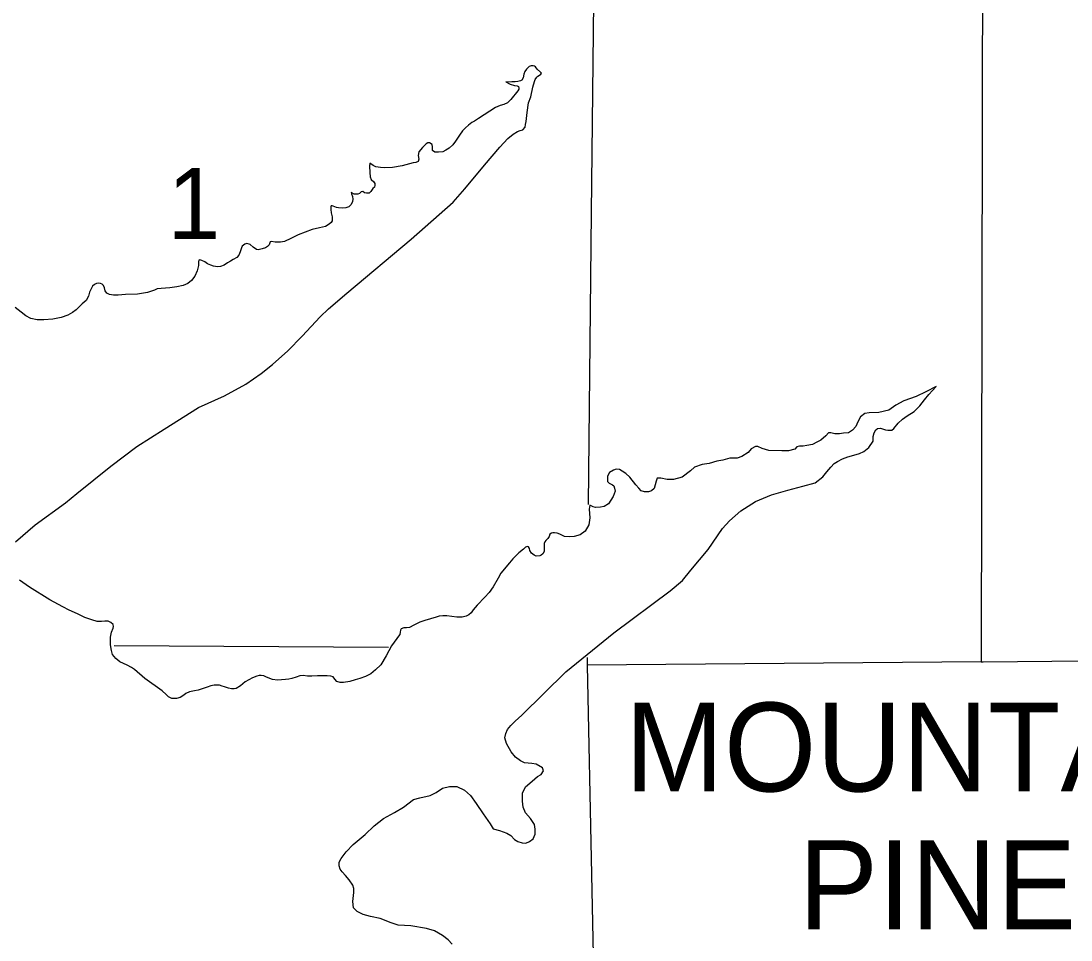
# Model space of a CAD drawing. Extents: x -3711 to 825, y -151 to 1050.
# Drawn here: x -2988.5 to -2918.5, y 182.5 to 243.7 of the extents above; entities that cross this region are included whole.
import ezdxf

# ---------------------------------------------------------------- set-up
doc = ezdxf.new("R2010")
doc.units = 0
for name, color, linetype in [('Level 4', 7, 'Continuous'), ('Level 5', 7, 'Continuous'), ('Level 6', 7, 'Continuous'), ('Level 8', 7, 'Continuous'), ('Level 9', 7, 'Continuous')]:
    doc.layers.add(name, color=color, linetype=linetype)

msp = doc.modelspace()

# ---------------------------------------------------------------- linework, layer by layer
at = {"layer": 'Level 4'}
for points in [[(-2950.175, 261.044), (-2950.506, 230.924), (-2950.697, 211.501)], [(-2950.779, 201.309), (-2950.769, 200.81)]]:
    msp.add_lwpolyline(points, dxfattribs=at)
at = {"layer": 'Level 5'}
for points in [[(-2982.284, 202.115), (-2964.011, 201.995)], [(-2924.536, 201.01), (-2924.406, 201.011), (-2894.609, 201.313), (-2891.85, 201.33)]]:
    msp.add_lwpolyline(points, dxfattribs=at)
at = {"layer": 'Level 8'}
msp.add_lwpolyline([(-2920.796, 270.225), (-2921.112, 260.629), (-2924.417, 260.676), (-2924.536, 201.01), (-2950.769, 200.81), (-2949.901, 158.971)], dxfattribs=at)
at = {"layer": 'Level 9'}
for points in [[(-2968.001, 224.542), (-2966.788, 225.572), (-2962.487, 229.167), (-2959.696, 231.639), (-2958.918, 232.532), (-2957.614, 234.112), (-2956.585, 235.303), (-2956.058, 235.875), (-2955.692, 236.173), (-2955.418, 236.356), (-2955.235, 236.425), (-2955.052, 236.471), (-2954.892, 236.631), (-2954.869, 236.814), (-2954.846, 237.02), (-2954.777, 237.615), (-2954.686, 238.256), (-2954.525, 238.669), (-2954.385, 239.298), (-2954.27, 239.677), (-2954.235, 239.815), (-2954.132, 239.965), (-2954.052, 240.034), (-2953.948, 240.114), (-2953.856, 240.172), (-2953.81, 240.229), (-2953.879, 240.298), (-2954.098, 240.505), (-2954.224, 240.652), (-2954.281, 240.698), (-2954.362, 240.721), (-2954.511, 240.721), (-2954.637, 240.675), (-2954.821, 240.514), (-2954.925, 240.353), (-2954.982, 240.169), (-2955.028, 239.916), (-2955.12, 239.778), (-2955.223, 239.732), (-2955.384, 239.686), (-2955.568, 239.652), (-2955.786, 239.652), (-2956.028, 239.64), (-2956.188, 239.663), (-2955.901, 239.514), (-2955.602, 239.422), (-2955.43, 239.399), (-2955.35, 239.342), (-2955.327, 239.238), (-2955.327, 239.169), (-2955.396, 239.066), (-2955.867, 238.491), (-2956.085, 238.261), (-2956.315, 238.146), (-2956.567, 238.088), (-2956.878, 237.95), (-2958.015, 237.215), (-2958.268, 237.031), (-2958.451, 236.939), (-2958.681, 236.778), (-2958.877, 236.605), (-2959.072, 236.387), (-2959.267, 236.111), (-2959.531, 235.697), (-2959.727, 235.456), (-2959.956, 235.237), (-2960.175, 235.111), (-2960.381, 234.996), (-2960.669, 234.973), (-2960.91, 234.973), (-2961.071, 235.076), (-2961.082, 235.226), (-2961.082, 235.329), (-2961.105, 235.479), (-2961.266, 235.605), (-2961.381, 235.605), (-2961.496, 235.536), (-2961.749, 235.295), (-2961.978, 235.007), (-2962.024, 234.754), (-2961.99, 234.501), (-2962.036, 234.363), (-2962.174, 234.294), (-2962.357, 234.26), (-2963.104, 234.053), (-2963.736, 233.961), (-2964.253, 233.926), (-2964.54, 233.961), (-2964.839, 233.995), (-2965.023, 234.087), (-2965.172, 234.191), (-2965.241, 234.248), (-2965.264, 234.041), (-2965.252, 233.616), (-2965.229, 233.34), (-2965.149, 233.145), (-2964.988, 232.995), (-2964.908, 232.88), (-2964.908, 232.777), (-2964.942, 232.639), (-2965.057, 232.547)], [(-2965.057, 232.547), (-2965.183, 232.363), (-2965.298, 232.248), (-2965.459, 232.236), (-2965.597, 232.271), (-2965.712, 232.351), (-2965.815, 232.328), (-2965.93, 232.225), (-2966.045, 232.179), (-2966.171, 232.179), (-2966.286, 232.179), (-2966.436, 232.259), (-2966.482, 232.282), (-2966.47, 232.19), (-2966.401, 232.029), (-2966.39, 231.846), (-2966.401, 231.685), (-2966.482, 231.478), (-2966.642, 231.34), (-2966.849, 231.271), (-2967.079, 231.236), (-2967.332, 231.259), (-2967.458, 231.294), (-2967.573, 231.34), (-2967.688, 231.386), (-2967.757, 231.397), (-2967.826, 231.397), (-2967.837, 231.34), (-2967.849, 231.144), (-2967.814, 230.937), (-2967.745, 230.673), (-2967.745, 230.523), (-2967.757, 230.408), (-2967.826, 230.293), (-2967.964, 230.167), (-2968.205, 230.029), (-2968.607, 229.926), (-2969.089, 229.811), (-2969.549, 229.65), (-2970.02, 229.466), (-2970.502, 229.213), (-2970.927, 229.029), (-2971.203, 228.971), (-2971.548, 228.971), (-2971.789, 229.029), (-2971.881, 228.994), (-2971.961, 228.81), (-2972.065, 228.695), (-2972.203, 228.603), (-2972.409, 228.523), (-2972.685, 228.477), (-2972.8, 228.488), (-2973.018, 228.638), (-2973.214, 228.822), (-2973.294, 228.856), (-2973.432, 228.879), (-2973.581, 228.845), (-2973.742, 228.718), (-2973.799, 228.603), (-2973.88, 228.327), (-2973.983, 228.109), (-2974.11, 227.948), (-2974.351, 227.822), (-2974.535, 227.718), (-2974.73, 227.592), (-2974.96, 227.454), (-2975.201, 227.362), (-2975.396, 227.339), (-2975.649, 227.373), (-2975.833, 227.442), (-2976.063, 227.534), (-2976.246, 227.672), (-2976.43, 227.764), (-2976.568, 227.81), (-2976.637, 227.776), (-2976.66, 227.672), (-2976.66, 227.419), (-2976.752, 227.074), (-2976.913, 226.706), (-2977.131, 226.419), (-2977.372, 226.235), (-2977.671, 226.086), (-2978.107, 226.005), (-2978.567, 225.925), (-2979.141, 225.89), (-2979.417, 225.867), (-2979.589, 225.787), (-2980.049, 225.626), (-2980.715, 225.511), (-2981.519, 225.488), (-2982.002, 225.442), (-2982.312, 225.442), (-2982.588, 225.488), (-2982.772, 225.591), (-2982.875, 225.741), (-2982.921, 225.936), (-2982.99, 226.086), (-2983.07, 226.189), (-2983.185, 226.235), (-2983.334, 226.247), (-2983.449, 226.235)], [(-2983.449, 226.235), (-2983.587, 226.155), (-2983.714, 226.04), (-2983.805, 225.867), (-2983.909, 225.637), (-2983.978, 225.384), (-2984.15, 225.097), (-2984.403, 224.878), (-2984.805, 224.476), (-2985.058, 224.292), (-2985.368, 224.108), (-2985.804, 223.959), (-2986.367, 223.855), (-2986.965, 223.798), (-2987.401, 223.798), (-2987.826, 223.89), (-2988.159, 224.074), (-2988.47, 224.304), (-2988.86, 224.625)], [(-2988.843, 209.024), (-2987.539, 210.157), (-2985.526, 211.611), (-2984.759, 212.241), (-2982.506, 214.055), (-2980.767, 215.36), (-2978.937, 216.528), (-2976.649, 217.97), (-2974.933, 218.749), (-2973.515, 219.527), (-2972.485, 220.237), (-2971.73, 220.832), (-2970.701, 221.748), (-2969.763, 222.71), (-2968.55, 224.015), (-2968.001, 224.542)], [(-2945.252, 205.747), (-2944.414, 206.442), (-2943.863, 207.137), (-2942.714, 208.503), (-2941.756, 209.893), (-2941.301, 210.42), (-2940.534, 211.091), (-2939.553, 211.691), (-2938.499, 212.146), (-2937.397, 212.458), (-2936.415, 212.721), (-2935.577, 212.937), (-2935.074, 213.344), (-2934.811, 213.68), (-2934.547, 213.991), (-2934.332, 214.231), (-2934.092, 214.375), (-2933.757, 214.543), (-2933.422, 214.686), (-2933.014, 214.782), (-2932.631, 214.902), (-2932.344, 215.022), (-2932.009, 215.31), (-2931.721, 215.717), (-2931.721, 216.029), (-2931.649, 216.268), (-2931.554, 216.484), (-2931.434, 216.556), (-2931.242, 216.58), (-2930.907, 216.484), (-2930.739, 216.46), (-2930.476, 216.46), (-2930.356, 216.556), (-2930.069, 216.915), (-2929.781, 217.179), (-2929.47, 217.419), (-2928.991, 217.706), (-2928.608, 218.066), (-2928.297, 218.473), (-2928.009, 218.833), (-2927.53, 219.36), (-2928.225, 219.001), (-2928.871, 218.689), (-2929.686, 218.401), (-2930.212, 218.114), (-2930.691, 217.778), (-2931.338, 217.635), (-2931.985, 217.611), (-2932.272, 217.563), (-2932.559, 217.347), (-2932.751, 217.011), (-2932.871, 216.7), (-2933.11, 216.46), (-2933.374, 216.268), (-2933.709, 216.244), (-2933.972, 216.22), (-2934.284, 216.22), (-2934.547, 216.268), (-2934.691, 216.268), (-2934.883, 216.077), (-2935.218, 215.789), (-2935.481, 215.645), (-2935.769, 215.501), (-2936.152, 215.429), (-2936.391, 215.382), (-2936.631, 215.382), (-2936.798, 215.334), (-2936.942, 215.19), (-2937.373, 215.07), (-2937.804, 215.07), (-2938.666, 215.094), (-2939.121, 215.238), (-2939.409, 215.358), (-2939.553, 215.358), (-2939.84, 215.214), (-2940.055, 214.974), (-2940.463, 214.71), (-2940.774, 214.591), (-2941.061, 214.591), (-2941.277, 214.591), (-2941.732, 214.447), (-2942.139, 214.399), (-2942.642, 214.231), (-2943.121, 214.159), (-2943.624, 213.991), (-2943.887, 213.752), (-2944.438, 213.32), (-2945.013, 213.177), (-2945.444, 213.177), (-2945.875, 213.248), (-2946.067, 213.248), (-2946.115, 213.248), (-2946.186, 213.057), (-2946.234, 212.817), (-2946.306, 212.577), (-2946.498, 212.41), (-2946.689, 212.338), (-2946.953, 212.338), (-2947.168, 212.41), (-2947.336, 212.601), (-2947.528, 212.817)], [(-2947.528, 212.817), (-2947.935, 213.32), (-2948.198, 213.56), (-2948.438, 213.728), (-2948.629, 213.824), (-2948.845, 213.848), (-2949.012, 213.8), (-2949.276, 213.632), (-2949.372, 213.488), (-2949.42, 213.368), (-2949.42, 213.2), (-2949.42, 213.033), (-2949.3, 212.913), (-2949.084, 212.817), (-2948.988, 212.745), (-2948.941, 212.601), (-2948.917, 212.386), (-2949.036, 212.026), (-2949.348, 211.547), (-2949.635, 211.379), (-2949.875, 211.331), (-2950.21, 211.307), (-2950.378, 211.355), (-2950.593, 211.451), (-2950.641, 211.187), (-2950.593, 210.612), (-2950.665, 210.157), (-2950.904, 209.725), (-2951.24, 209.486), (-2951.647, 209.366), (-2951.975, 209.344), (-2952.272, 209.379), (-2952.592, 209.516), (-2952.775, 209.585), (-2952.958, 209.608), (-2953.061, 209.619), (-2953.153, 209.596), (-2953.256, 209.527), (-2953.313, 209.367), (-2953.393, 209.23), (-2953.519, 209.115), (-2953.599, 209.012), (-2953.633, 208.898), (-2953.633, 208.715), (-2953.633, 208.554), (-2953.645, 208.371), (-2953.725, 208.211), (-2953.828, 208.119), (-2953.919, 208.074), (-2954.159, 208.051), (-2954.308, 208.119), (-2954.48, 208.268), (-2954.583, 208.44), (-2954.617, 208.566), (-2954.674, 208.692), (-2954.743, 208.715), (-2954.869, 208.657), (-2955.006, 208.52), (-2955.326, 208.291), (-2955.727, 207.879), (-2955.944, 207.627), (-2956.516, 206.917), (-2956.71, 206.597), (-2957.042, 206.024), (-2957.294, 205.635), (-2957.58, 205.337), (-2958.095, 204.788), (-2958.369, 204.49), (-2958.506, 204.284), (-2958.644, 204.158), (-2958.827, 204.067), (-2959.101, 203.998), (-2959.456, 203.998), (-2960.108, 204.09), (-2960.382, 204.09), (-2960.623, 204.067), (-2960.84, 203.987), (-2961.595, 203.781), (-2961.927, 203.655), (-2962.327, 203.471), (-2962.613, 203.311), (-2962.796, 203.277), (-2962.979, 203.277), (-2963.151, 203.22), (-2963.196, 203.128), (-2963.219, 202.991), (-2963.254, 202.853), (-2963.334, 202.727), (-2963.448, 202.578), (-2963.814, 202.098), (-2964.169, 201.422), (-2964.523, 200.827), (-2964.867, 200.483), (-2965.175, 200.22), (-2965.541, 200.037), (-2965.919, 199.9), (-2966.216, 199.819), (-2966.571, 199.716), (-2966.994, 199.648), (-2967.234, 199.636), (-2967.452, 199.716)], [(-2967.452, 199.716), (-2967.578, 199.865), (-2967.692, 200.014), (-2967.841, 200.071), (-2968.081, 200.083), (-2968.356, 200.083), (-2968.733, 200.083), (-2969.11, 200.06), (-2969.408, 200.071), (-2969.694, 200.106), (-2969.911, 200.094), (-2970.163, 200.003), (-2970.449, 199.911), (-2970.643, 199.865), (-2970.861, 199.842), (-2971.135, 199.819), (-2971.398, 199.808), (-2971.719, 199.842), (-2971.902, 199.9), (-2972.165, 200.026), (-2972.302, 200.083), (-2972.485, 200.106), (-2972.622, 200.106), (-2972.782, 200.071), (-2973.057, 199.945), (-2973.549, 199.694), (-2973.869, 199.43), (-2974.144, 199.236), (-2974.281, 199.213), (-2974.464, 199.213), (-2974.659, 199.27), (-2974.922, 199.35), (-2975.093, 199.407), (-2975.265, 199.465), (-2975.425, 199.465), (-2975.608, 199.465), (-2975.837, 199.419), (-2976.077, 199.327), (-2976.409, 199.213), (-2976.672, 199.144), (-2976.935, 199.098), (-2977.255, 199.018), (-2977.495, 198.904), (-2977.644, 198.801), (-2977.873, 198.652), (-2978.125, 198.583), (-2978.433, 198.572), (-2978.662, 198.698), (-2978.822, 198.846), (-2979.074, 199.098), (-2980.241, 199.911), (-2980.916, 200.506), (-2981.11, 200.644), (-2981.408, 200.793), (-2981.888, 201.022), (-2982.163, 201.239), (-2982.391, 201.502), (-2982.46, 201.766), (-2982.517, 202.155), (-2982.517, 202.659), (-2982.449, 203.002), (-2982.334, 203.254), (-2982.311, 203.368), (-2982.334, 203.506), (-2982.494, 203.643), (-2982.677, 203.723), (-2982.906, 203.735), (-2983.124, 203.712), (-2983.409, 203.712), (-2983.764, 203.826), (-2984.233, 203.964), (-2984.725, 204.216), (-2985.274, 204.467), (-2985.686, 204.685), (-2986.555, 205.154), (-2987.905, 205.99), (-2988.58, 206.459)], [(-2959.766, 182.21), (-2960.029, 182.498), (-2960.412, 182.786), (-2960.939, 183.097), (-2961.466, 183.265), (-2962.52, 183.433), (-2963.358, 183.481), (-2963.837, 183.624), (-2964.555, 183.912), (-2965.202, 184.056), (-2965.681, 184.2), (-2966.088, 184.391), (-2966.328, 184.631), (-2966.375, 185.063), (-2966.304, 185.662), (-2966.304, 185.925), (-2966.375, 186.141), (-2966.615, 186.501), (-2966.878, 186.788), (-2967.094, 187.028), (-2967.214, 187.22), (-2967.286, 187.435), (-2967.286, 187.675), (-2967.166, 187.915), (-2966.83, 188.37), (-2966.351, 188.849), (-2965.561, 189.521), (-2964.962, 190.096), (-2964.34, 190.575), (-2963.597, 190.983), (-2962.999, 191.342), (-2962.328, 191.845), (-2961.921, 191.965), (-2961.226, 192.109), (-2960.819, 192.325), (-2960.412, 192.612), (-2959.933, 192.708), (-2959.454, 192.708), (-2958.951, 192.469), (-2958.544, 192.109), (-2958.161, 191.582), (-2957.706, 190.887), (-2957.227, 190.24), (-2957.035, 189.904), (-2956.604, 189.784), (-2956.125, 189.616), (-2955.862, 189.449), (-2955.622, 189.185), (-2955.383, 189.041), (-2955.095, 188.969), (-2954.856, 188.945), (-2954.616, 189.041), (-2954.377, 189.233), (-2954.233, 189.544), (-2954.233, 189.88), (-2954.281, 190.192), (-2954.545, 190.575), (-2954.88, 190.959), (-2955.024, 191.342), (-2955.072, 191.75), (-2955.072, 192.277), (-2954.88, 192.684), (-2954.425, 193.068), (-2954.09, 193.379), (-2953.826, 193.523), (-2953.682, 193.763), (-2953.754, 193.955), (-2954.161, 194.194), (-2954.449, 194.242), (-2954.952, 194.29), (-2955.215, 194.434), (-2955.55, 194.674), (-2955.838, 195.033), (-2956.149, 195.584), (-2956.245, 195.968), (-2956.197, 196.255), (-2956.077, 196.519), (-2955.862, 196.783), (-2955.574, 197.07), (-2955.119, 197.478), (-2952.198, 200.354), (-2948.988, 202.942), (-2945.252, 205.747)]]:
    msp.add_lwpolyline(points, dxfattribs=at)

# ---------------------------------------------------------------- texts
at = {"layer": 'Level 5'}
msp.add_text('1', height=4.734, dxfattribs=at).set_placement((-2978.727, 229.187))
at = {"layer": 'Level 6'}
for s, p in [('MOUNTAIN', (-2948.257, 192.387)), ('PINE', (-2936.681, 183.206))]:
    msp.add_text(s, height=5.9179, dxfattribs=at).set_placement(p)

doc.saveas('drawing.dxf')
